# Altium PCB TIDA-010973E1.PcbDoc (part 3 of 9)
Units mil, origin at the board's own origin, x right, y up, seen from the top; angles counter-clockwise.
Board outline 5166 x 3669 mil, 8 copper layers (L01 - TOP, L02 - GND, L03 - SIG, L04 - GND, L05 - PWR, L06 - SIG, L07 - GND, L08 - BOTTOM), stack 61.7 mil thick; 677 components, 493 nets, 2522 pads, 1424 vias.
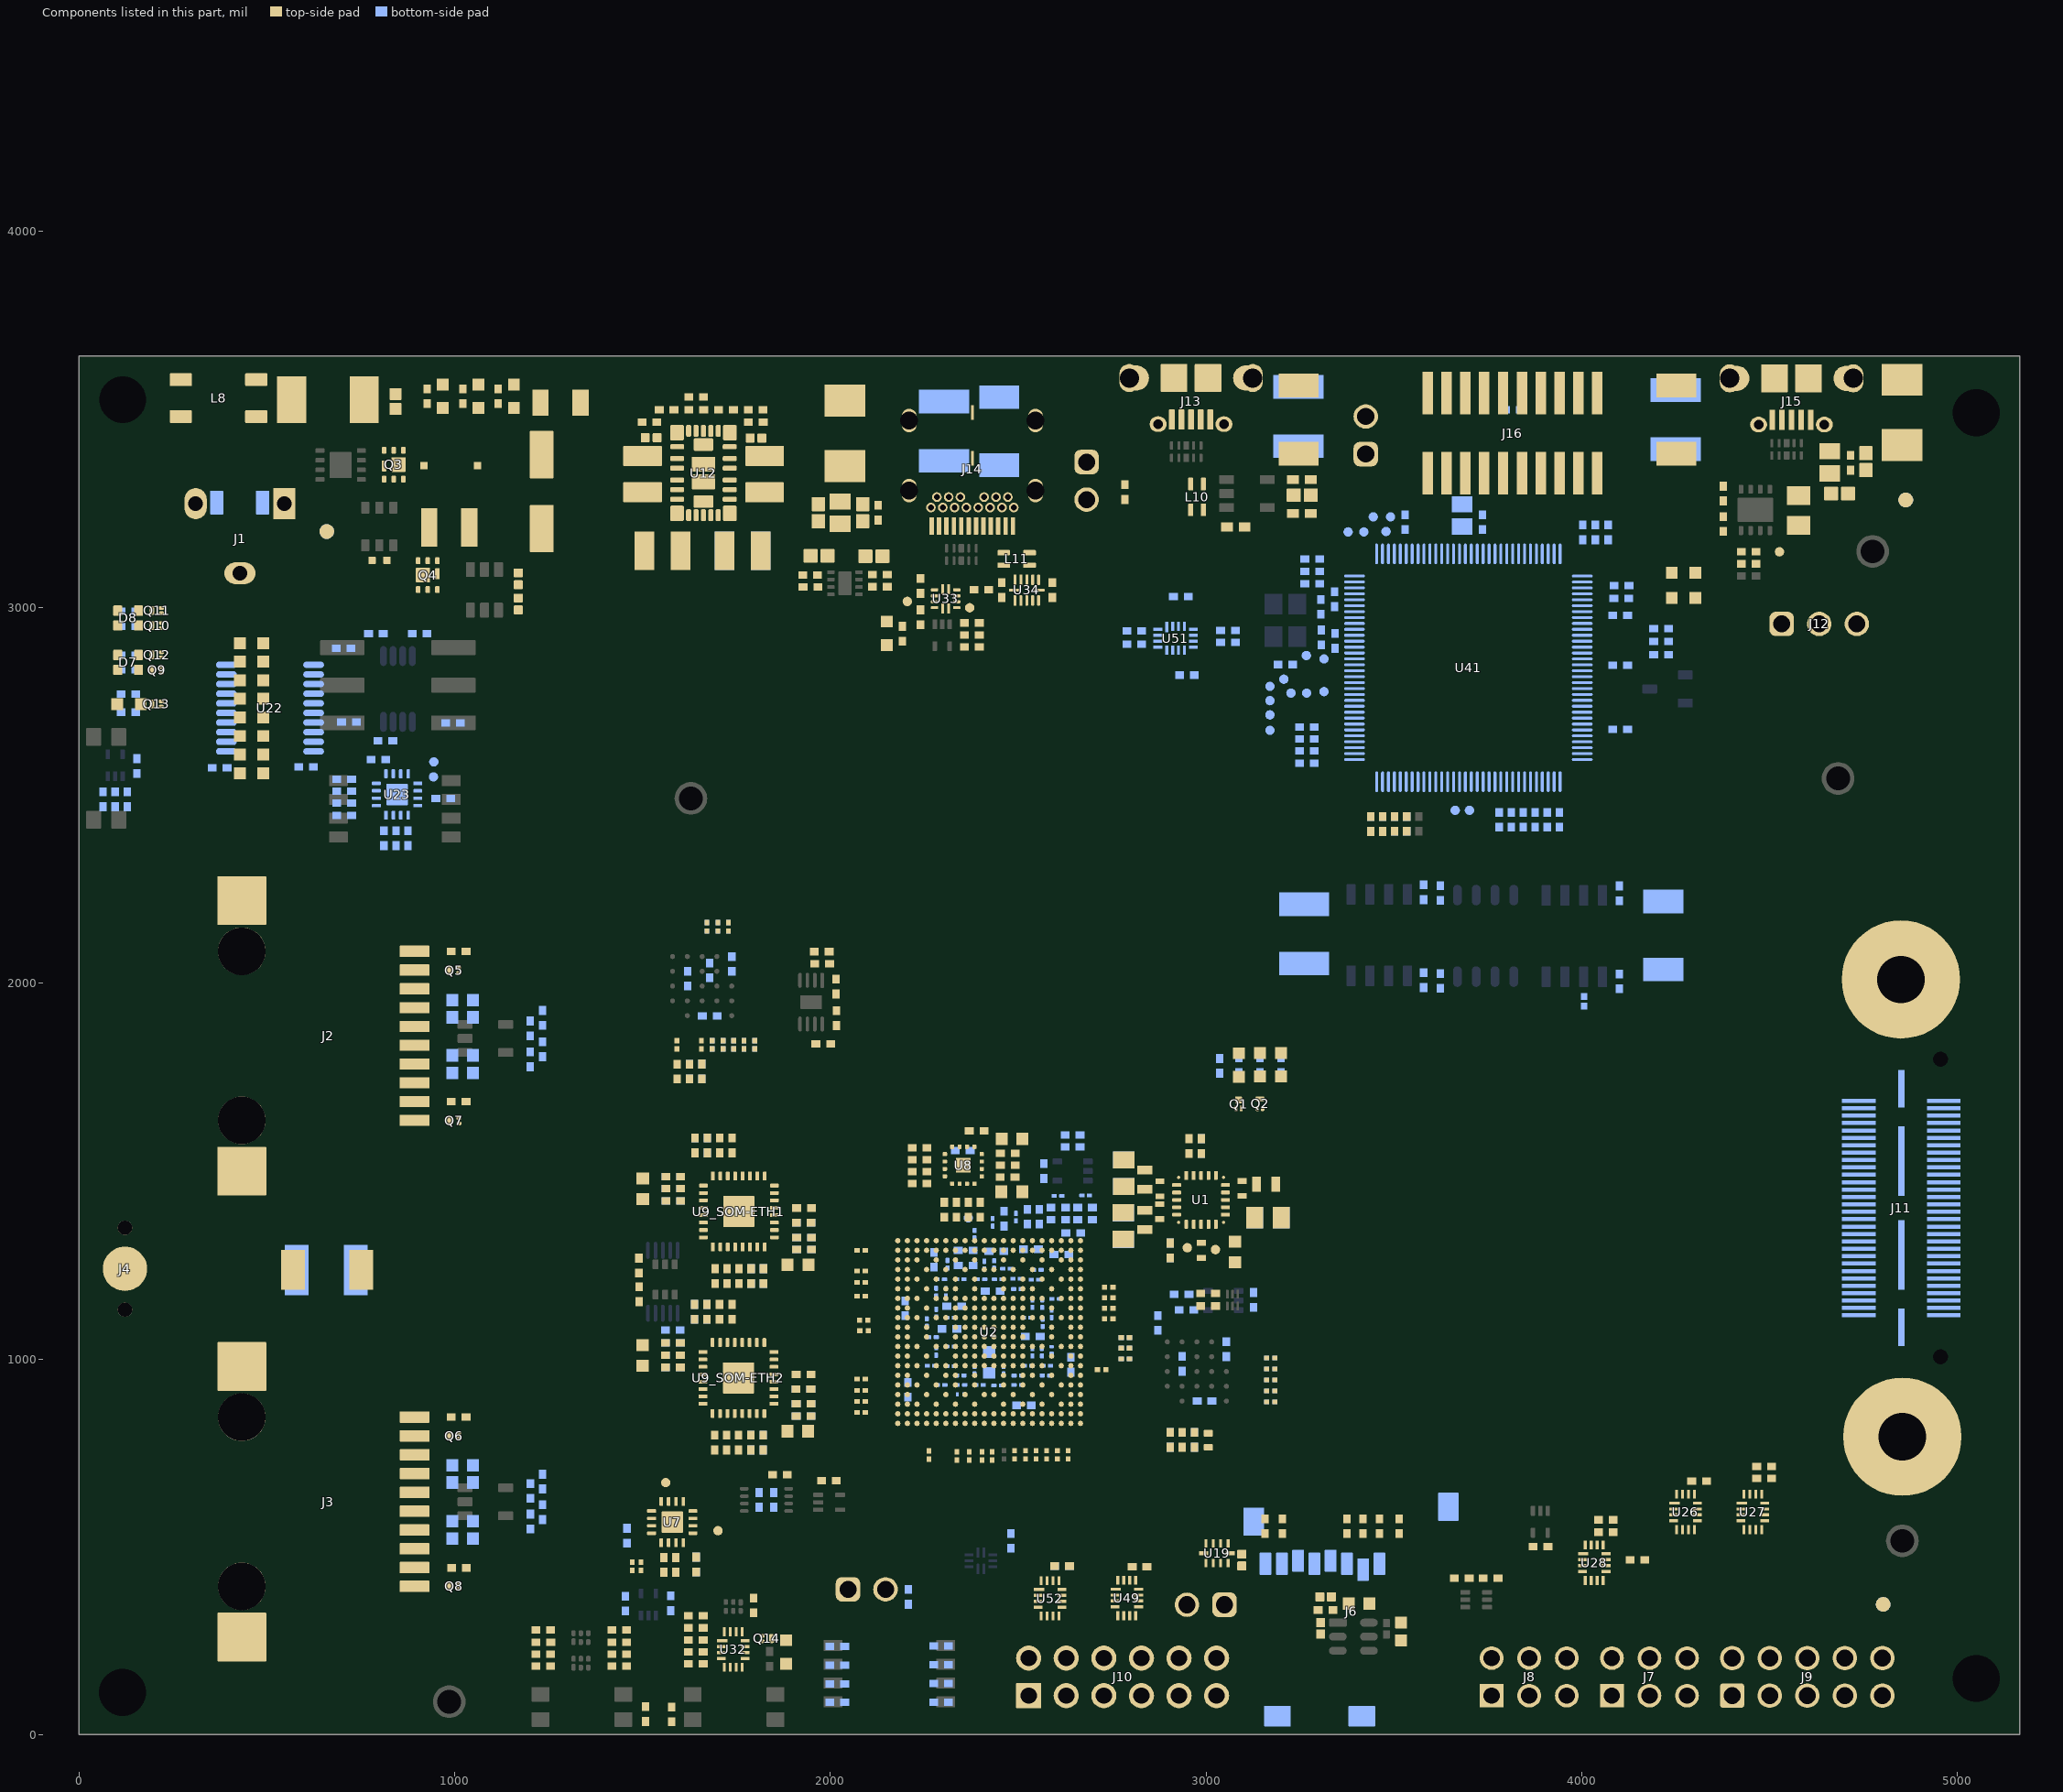
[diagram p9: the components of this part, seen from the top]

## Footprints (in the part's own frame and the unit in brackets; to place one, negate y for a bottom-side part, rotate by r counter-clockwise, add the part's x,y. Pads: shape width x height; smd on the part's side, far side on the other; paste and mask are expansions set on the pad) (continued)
PDT0128A [mm] "Thin QFP, 128-Leads, Body 14x14mm, Pitch 0.4mm"
  oval 1.4x0.2 smd: 1(-7.7,6.2) 2(-7.7,5.8) 3(-7.7,5.4) 4(-7.7,5) 5(-7.7,4.6) 6(-7.7,4.2) 7(-7.7,3.8) 8(-7.7,3.4) 9(-7.7,3) 10(-7.7,2.6) 11(-7.7,2.2) 12(-7.7,1.8) 13(-7.7,1.4) 14(-7.7,1) 15(-7.7,0.6) 16(-7.7,0.2) 17(-7.7,-0.2) 18(-7.7,-0.6) 19(-7.7,-1) 20(-7.7,-1.4) 21(-7.7,-1.8) 22(-7.7,-2.2) 23(-7.7,-2.6) 24(-7.7,-3) 25(-7.7,-3.4) 26(-7.7,-3.8) 27(-7.7,-4.2) 28(-7.7,-4.6) 29(-7.7,-5) 30(-7.7,-5.4) 31(-7.7,-5.8) 32(-7.7,-6.2) 65(7.7,-6.2) 66(7.7,-5.8) 67(7.7,-5.4) 68(7.7,-5) 69(7.7,-4.6) 70(7.7,-4.2) 71(7.7,-3.8) 72(7.7,-3.4) 73(7.7,-3) 74(7.7,-2.6) 75(7.7,-2.2) 76(7.7,-1.8) 77(7.7,-1.4) 78(7.7,-1) 79(7.7,-0.6) 80(7.7,-0.2) 81(7.7,0.2) 82(7.7,0.6) 83(7.7,1) 84(7.7,1.4) 85(7.7,1.8) 86(7.7,2.2) 87(7.7,2.6) 88(7.7,3) 89(7.7,3.4) 90(7.7,3.8) 91(7.7,4.2) 92(7.7,4.6) 93(7.7,5) 94(7.7,5.4) 95(7.7,5.8) 96(7.7,6.2)
  oval 0.2x1.4 smd: 33(-6.2,-7.7) 34(-5.8,-7.7) 35(-5.4,-7.7) 36(-5,-7.7) 37(-4.6,-7.7) 38(-4.2,-7.7) 39(-3.8,-7.7) 40(-3.4,-7.7) 41(-3,-7.7) 42(-2.6,-7.7) 43(-2.2,-7.7) 44(-1.8,-7.7) 45(-1.4,-7.7) 46(-1,-7.7) 47(-0.6,-7.7) 48(-0.2,-7.7) 49(0.2,-7.7) 50(0.6,-7.7) 51(1,-7.7) 52(1.4,-7.7) 53(1.8,-7.7) 54(2.2,-7.7) 55(2.6,-7.7) 56(3,-7.7) 57(3.4,-7.7) 58(3.8,-7.7) 59(4.2,-7.7) 60(4.6,-7.7) 61(5,-7.7) 62(5.4,-7.7) 63(5.8,-7.7) 64(6.2,-7.7) 97(6.2,7.7) 98(5.8,7.7) 99(5.4,7.7) 100(5,7.7) 101(4.6,7.7) 102(4.2,7.7) 103(3.8,7.7) 104(3.4,7.7) 105(3,7.7) 106(2.6,7.7) 107(2.2,7.7) 108(1.8,7.7) 109(1.4,7.7) 110(1,7.7) 111(0.6,7.7) 112(0.2,7.7) 113(-0.2,7.7) 114(-0.6,7.7) 115(-1,7.7) 116(-1.4,7.7) 117(-1.8,7.7) 118(-2.2,7.7) 119(-2.6,7.7) 120(-3,7.7) 121(-3.4,7.7) 122(-3.8,7.7) 123(-4.2,7.7) 124(-4.6,7.7) 125(-5,7.7) 126(-5.4,7.7) 127(-5.8,7.7) 128(-6.2,7.7)
  silkscreen extent -7.7,-6.3 6.3,6.99, body extent -8,-8 8,8, height 1.07
PW0020A_N [mm] "TSOP, 20-Leads, Body 6.5x4.4mm, Pitch 0.65mm, IPC Medium Density"
  oval 1.4x0.45 smd: 1(-2.95,2.925) 2(-2.95,2.275) 3(-2.95,1.625) 4(-2.95,0.975) 5(-2.95,0.325) 6(-2.95,-0.325) 7(-2.95,-0.975) 8(-2.95,-1.625) 9(-2.95,-2.275) 10(-2.95,-2.925) 11(2.95,-2.925) 12(2.95,-2.275) 13(2.95,-1.625) 14(2.95,-0.975) 15(2.95,-0.325) 16(2.95,0.325) 17(2.95,0.975) 18(2.95,1.625) 19(2.95,2.275) 20(2.95,2.925)
  Top Overlay keep-out lines w0.2: -1.85,-3.3 1.85,-3.3
  silkscreen extent -3.5,-3.3 1.85,3.4, body extent -3.21,-3.25 3.21,3.25, height 1
RDH0030A-MFG [mm]
  rrect22% 0.93x1.05 smd paste-1000 mask-1000: 1(-1.786,2.725) 8(-1.786,-2.725) 14(1.786,-2.725) 21(1.786,2.725)
  rrect57% 0.95x0.35 smd paste-1000 mask-1000: 2(-1.775,1.775) 3(-1.775,0.975) 4(-1.775,0.325) 5(-1.775,-0.475) 6(-1.775,-1.125) 7(-1.775,-1.775) 15(1.775,-1.775) 16(1.775,-1.125) 17(1.775,-0.475) 18(1.775,0.325) 19(1.775,0.975) 20(1.775,1.775)
  rrect57% 0.35x0.8 smd paste-1000 mask-1000: 9(-1,-2.85) 10(-0.5,-2.85) 11(0,-2.85) 12(0.5,-2.85) 13(1,-2.85) 22(1,2.85) 23(0.5,2.85) 24(0,2.85) 25(-0.5,2.85) 26(-1,2.85)
  rrect24% 1.35x0.84 smd paste-1000 mask-1000: 27(0,1.925) 30(0,-1.925)
  rrect12% 1.6x1 smd paste-1000 mask-1000: 28(0,0.6) 29(0,-0.6)
  L01 - TOP region: -0.85,-1.05 -0.85,1.05 -0.837,1.1 -0.8,1.137 -0.75,1.15 -0.75,1.15 0.75,1.15 0.8,1.137 0.837,1.1 0.85,1.05 0.85,1.05 0.85,-1.05 0.837,-1.1 0.8,-1.137 0.75,-1.15 0.75,-1.15 -0.75,-1.15 -0.8,-1.137 -0.837,-1.1 -0.85,-1.05
  silkscreen extent -2.95,-3.65 2.05,3.65, body extent -2.35,-3.35 2.35,3.35, height 0.25
RER0016A-MFG [mm] "Recommended Land Pattern"
  rrect36% 0.3x0.275 smd paste-1000 mask+0: 1(-1.25,0.75) 2(-1.25,0.25) 3(-1.25,-0.25) 4(-1.25,-0.75) 9(1.25,-0.75) 10(1.25,-0.25) 11(1.25,0.25) 12(1.25,0.75)
  rrect36% 0.275x0.3 smd paste-1000 mask+0: 5(-0.75,-1.25) 6(-0.25,-1.25) 7(0.25,-1.25) 8(0.75,-1.25) 13(0.75,1.25) 14(0.25,1.25) 15(-0.25,1.25) 16(-0.75,1.25)
  rrect10% 1x1 smd paste-1000 mask+0: 17(0,0)
  silkscreen extent -2.15,-1.55 1.55,1.55, body extent -1.5,-1.5 1.5,1.5, height 1.5
RGT0016A#1 [mm] "QFN, 16-Leads, Body 3x3mm, Pitch 0.5mm, Thermal Pad 1.45x1.45mm, TI Recommended"
  rrect42% 0.6x0.24 smd: 1(-1.4,0.75) 2(-1.4,0.25) 3(-1.4,-0.25) 4(-1.4,-0.75) 9(1.4,-0.75) 10(1.4,-0.25) 11(1.4,0.25) 12(1.4,0.75)
  rrect42% 0.24x0.6 smd: 5(-0.75,-1.4) 6(-0.25,-1.4) 7(0.25,-1.4) 8(0.75,-1.4) 13(0.75,1.4) 14(0.25,1.4) 15(-0.25,1.4) 16(-0.75,1.4)
  rrect7% 1.34x1.34 on Top Paste: 17(0,0)
  rrect7% 1.45x1.45 smd paste-0.725: 17(0,0)
  silkscreen extent -1.72,-1.73 1.72,1.73, body extent -1.5,-1.5 1.5,1.5, height 1
RGT0016A#2 [mm] "QFN, 16-Leads, Body 3x3mm, Pitch 0.5mm, Thermal Pad 1.45x1.45mm, TI Recommended"
  rrect42% 0.6x0.24 smd: 1(-1.4,0.75) 2(-1.4,0.25) 3(-1.4,-0.25) 4(-1.4,-0.75) 9(1.4,-0.75) 10(1.4,-0.25) 11(1.4,0.25) 12(1.4,0.75)
  rrect42% 0.24x0.6 smd: 5(-0.75,-1.4) 6(-0.25,-1.4) 7(0.25,-1.4) 8(0.75,-1.4) 13(0.75,1.4) 14(0.25,1.4) 15(-0.25,1.4) 16(-0.75,1.4)
  rrect7% 1.34x1.34 on Bottom Paste: 17(0,0)
  rrect7% 1.45x1.45 smd paste-0.725: 17(0,0)
  silkscreen extent -1.72,-1.73 1.72,1.73, body extent -1.5,-1.5 1.5,1.5, height 1
RHB0032M-MFG [mm] "Recommended Land Pattern"
  rrect40% 0.6x0.25 smd paste+0 mask+0: 1(-2.4,1.75) 2(-2.4,1.25) 3(-2.4,0.75) 4(-2.4,0.25) 5(-2.4,-0.25) 6(-2.4,-0.75) 7(-2.4,-1.25) 8(-2.4,-1.75) 17(2.4,-1.75) 18(2.4,-1.25) 19(2.4,-0.75) 20(2.4,-0.25) 21(2.4,0.25) 22(2.4,0.75) 23(2.4,1.25) 24(2.4,1.75)
  rrect40% 0.25x0.6 smd paste+0 mask+0: 9(-1.75,-2.4) 10(-1.25,-2.4) 11(-0.75,-2.4) 12(-0.25,-2.4) 13(0.25,-2.4) 14(0.75,-2.4) 15(1.25,-2.4) 16(1.75,-2.4) 25(1.75,2.4) 26(1.25,2.4) 27(0.75,2.4) 28(0.25,2.4) 29(-0.25,2.4) 30(-0.75,2.4) 31(-1.25,2.4) 32(-1.75,2.4)
  rrect5% 2.1x2.1 smd paste-1000 mask+0: 33(0,0)
  silkscreen extent -3.37,-2.55 2.55,2.55, body extent -2.8,-2.8 2.8,2.8, height 0.25
RSE0010A [mm] "QFN, 10-Leads, Body 1.5x2mm, Pitch 0.5mm, TI Recommended"
  rect 0.55x0.2 smd: 1(-0.675,0.75) 2(-0.675,0.25) 3(-0.675,-0.25) 4(-0.675,-0.75) 6(0.675,-0.75) 7(0.675,-0.25) 8(0.675,0.25) 9(0.675,0.75)
  rect 0.3x0.6 smd: 5(0,-0.9) 10(0,0.9)
  silkscreen extent -1.07,-1.17 0.77,1.18, body extent -0.77,-1.02 0.78,1.03, height 0.61
RSV0016A [mm] "QFN, 16-Leads, Body 1.8x2.6mm, Pitch 0.4mm, TI Recommended"
  rect 0.7x0.2 smd: 1(-0.75,0.6)
  rect 0.6x0.2 smd: 2(-0.8,0.2) 3(-0.8,-0.2) 4(-0.8,-0.6) 9(0.8,-0.6) 10(0.8,-0.2) 11(0.8,0.2) 12(0.8,0.6)
  rect 0.2x0.6 smd: 5(-0.6,-1.2) 6(-0.2,-1.2) 7(0.2,-1.2) 8(0.6,-1.2) 13(0.6,1.2) 14(0.2,1.2) 15(-0.2,1.2) 16(-0.6,1.2)
  silkscreen extent -1.08,-1.33 1.08,1.45, body extent -0.92,-1.32 0.92,1.33, height 0.56
RUT0012A [mm] "QFN, 12-Leads, Body 1.7x2mm, Pitch 0.4mm, TI Recommended"
  rrect50% 0.7x0.2 smd: 1(-0.7,0.8) 2(-0.7,0.4) 3(-0.7,0) 4(-0.7,-0.4) 5(-0.7,-0.8) 7(0.7,-0.8) 8(0.7,-0.4) 9(0.7,0) 10(0.7,0.4) 11(0.7,0.8)
  rrect50% 0.2x0.7 smd: 6(0,-0.85) 12(0,0.85)
  silkscreen extent -0.9,-1.2 0.9,1.2, body extent -0.85,-1 0.85,1, height 0.55
RWB0012A [mm] "QFN, 12-Leads, Body 1.6x1.6mm, Pitch 0.4mm"
  rrect57% 0.7x0.2 smd paste-0.1: 1(-0.65,0.2) 2(-0.65,-0.2) 7(0.65,-0.2) 8(0.65,0.2)
  rrect57% 0.2x0.5 smd: 3(-0.6,-0.75) 4(-0.2,-0.75) 5(0.2,-0.75) 6(0.6,-0.75) 9(0.6,0.75) 10(0.2,0.75) 11(-0.2,0.75) 12(-0.6,0.75)
  silkscreen extent -0.92,-0.91 0.92,0.91, body extent -0.8,-0.8 0.8,0.8, height 0.4
Samtec_FTR-110-51-x-D-06 [mm] "Header, 1.27mm, 10x2, SMT"
  rect 2.87x0.711 smd: 1(-2.705,5.715) 2(2.705,5.715) 3(-2.705,4.445) 4(2.705,4.445) 5(-2.705,3.175) 6(2.705,3.175) 7(-2.705,1.905) 8(2.705,1.905) 9(-2.705,0.635) 10(2.705,0.635) 11(-2.705,-0.635) 12(2.705,-0.635) 13(-2.705,-1.905) 14(2.705,-1.905) 15(-2.705,-3.175) 16(2.705,-3.175) 17(-2.705,-4.445) 18(2.705,-4.445) 19(-2.705,-5.715) 20(2.705,-5.715)
  silkscreen extent -2.49,-6.35 2.49,6.7, body extent -3.76,-6.35 3.76,6.35, height 8.64
Samtec_QSH-030-01-X-D-A [mm] "Receptacle, 0.5 mm, 30x2, TH"
  rect 2.27x0.279 smd: 1(-2.865,7.25) 2(2.865,7.25) 3(-2.865,6.75) 4(2.865,6.75) 5(-2.865,6.25) 6(2.865,6.25) 7(-2.865,5.75) 8(2.865,5.75) 9(-2.865,5.25) 10(2.865,5.25) 11(-2.865,4.75) 12(2.865,4.75) 13(-2.865,4.25) 14(2.865,4.25) 15(-2.865,3.75) 16(2.865,3.75) 17(-2.865,3.25) 18(2.865,3.25) 19(-2.865,2.75) 20(2.865,2.75) 21(-2.865,2.25) 22(2.865,2.25) 23(-2.865,1.75) 24(2.865,1.75) 25(-2.865,1.25) 26(2.865,1.25) 27(-2.865,0.75) 28(2.865,0.75) 29(-2.865,0.25) 30(2.865,0.25) 31(-2.865,-0.25) 32(2.865,-0.25) 33(-2.865,-0.75) 34(2.865,-0.75) 35(-2.865,-1.25) 36(2.865,-1.25) 37(-2.865,-1.75) 38(2.865,-1.75) 39(-2.865,-2.25) 40(2.865,-2.25) 41(-2.865,-2.75) 42(2.865,-2.75) 43(-2.865,-3.25) 44(2.865,-3.25) 45(-2.865,-3.75) 46(2.865,-3.75) 47(-2.865,-4.25) 48(2.865,-4.25) 49(-2.865,-4.75) 50(2.865,-4.75) 51(-2.865,-5.25) 52(2.865,-5.25) 53(-2.865,-5.75) 54(2.865,-5.75) 55(-2.865,-6.25) 56(2.865,-6.25) 57(-2.865,-6.75) 58(2.865,-6.75) 59(-2.865,-7.25) 60(2.865,-7.25)
  round 0 hole 1.02 unplated: MH1(2.67,10.065) MH2(2.67,-10.065)
  rect 0.43x2.54 smd: MP1(0,8.065) MP4(0,-8.065)
  rect 0.43x4.7 smd: MP2(0,3.175) MP3(0,-3.175)
  silkscreen extent -3.9,-10.66 3.62,10.66, body extent -3.75,-10.64 3.75,10.67, height 3.25
SloBlo452 [mm] "Littelfuse 452/4 Fuses, recommended land pattern"
  rect 1.96x3.15 smd: 1(-2.455,0) 2(2.455,0)
  silkscreen extent -3.75,-1.88 3.75,1.9, body extent -3.05,-1.35 3.05,1.34, height 2.69
SMB-Bi [mil] "Molded Diode, 2-Leads, Body 5.4x3.6mm, IPC Medium Density, based on OnSemi component dimensions"
  rect 85x107.99 smd: 1(-87.01,0) 2(87.01,0)
  silkscreen extent -125,-79 125,79, body extent -104,-73 104,73, height 89
TI_Stacked_Overlay_Small [mil]
  silkscreen extent -418,-98 418,98
TP_25MIL-SMT [mil]
  round 25 smd mask-2.5: 1(0,0)
VAF0024A-MFG [mm]
  round 0.207 smd paste+0 mask+0: 1(-1.519,1.519) 7(-1.519,-1.519) 13(1.519,-1.519) 19(1.519,1.519)
  rrect40% 0.6x0.25 smd paste+0 mask+0: 2(-1.65,1) 3(-1.65,0.5) 4(-1.65,0) 5(-1.65,-0.5) 6(-1.65,-1) 14(1.65,-1) 15(1.65,-0.5) 16(1.65,0) 17(1.65,0.5) 18(1.65,1)
  rrect40% 0.25x0.6 smd paste+0 mask+0: 8(-1,-1.65) 9(-0.5,-1.65) 11(0.5,-1.65) 12(1,-1.65) 20(1,1.65) 21(0.5,1.65) 23(-0.5,1.65) 24(-1,1.65)
  rrect40% 0.25x0.6 smd paste+0 mask-1000: 10(0,-1.65) 22(0,1.65)
  L01 - TOP region: -0.5,0.286 -0.493,0.311 -0.475,0.33 -0.45,0.336 -0.45,0.336 -0.1,0.336 -0.1,1.357 -0.118,1.375 -0.125,1.4 -0.125,1.4 -0.125,1.9 -0.118,1.925 -0.1,1.943 -0.075,1.95 -0.075,1.95 0.075,1.95 0.1,1.943 0.118,1.925 0.125,1.9 0.125,1.9 0.125,1.4 0.118,1.375 0.1,1.357 0.1,1.357 0.1,0.336 0.45,0.336 0.475,0.33 0.493,0.311 0.5,0.287 0.5,0.286 0.5,-0.286 0.493,-0.311 0.475,-0.33 0.45,-0.336 0.45,-0.336 0.1,-0.336 0.1,-1.357 0.118,-1.375 0.125,-1.4 0.125,-1.4 0.125,-1.9 0.118,-1.925 0.1,-1.943 0.075,-1.95 0.075,-1.95 -0.075,-1.95 -0.1,-1.943 -0.118,-1.925 -0.125,-1.9 -0.125,-1.9 -0.125,-1.4 -0.118,-1.375 -0.1,-1.357 -0.1,-1.357 -0.1,-0.336 -0.45,-0.336 -0.475,-0.33 -0.493,-0.311 -0.5,-0.287 -0.5,-0.286
  L01 - TOP region: -1.9,1.375 -1.919,1.379 -1.935,1.39 -1.946,1.406 -1.95,1.425 -1.95,1.425 -1.95,1.55 -1.943,1.575 -1.925,1.593 -1.9,1.6 -1.9,1.6 -1.6,1.6 -1.6,1.9 -1.593,1.925 -1.575,1.943 -1.55,1.95 -1.55,1.95 -1.425,1.95 -1.406,1.946 -1.39,1.935 -1.379,1.919 -1.375,1.9 -1.375,1.9 -1.375,1.425 -1.379,1.406 -1.39,1.39 -1.406,1.379 -1.425,1.375 -1.425,1.375
  L01 - TOP region: -1.9,-1.375 -1.919,-1.379 -1.935,-1.39 -1.946,-1.406 -1.95,-1.425 -1.95,-1.425 -1.95,-1.55 -1.946,-1.569 -1.935,-1.585 -1.919,-1.596 -1.9,-1.6 -1.9,-1.6 -1.6,-1.6 -1.6,-1.9 -1.596,-1.919 -1.585,-1.935 -1.569,-1.946 -1.55,-1.95 -1.55,-1.95 -1.425,-1.95 -1.4,-1.943 -1.382,-1.925 -1.375,-1.9 -1.375,-1.9 -1.375,-1.425 -1.379,-1.406 -1.39,-1.39 -1.406,-1.379 -1.425,-1.375 -1.425,-1.375
  L01 - TOP region: 1.9,-1.375 1.919,-1.379 1.935,-1.39 1.946,-1.406 1.95,-1.425 1.95,-1.425 1.95,-1.55 1.946,-1.569 1.935,-1.585 1.919,-1.596 1.9,-1.6 1.9,-1.6 1.6,-1.6 1.6,-1.9 1.596,-1.919 1.585,-1.935 1.569,-1.946 1.55,-1.95 1.55,-1.95 1.425,-1.95 1.4,-1.943 1.382,-1.925 1.375,-1.9 1.375,-1.9 1.375,-1.425 1.379,-1.406 1.39,-1.39 1.406,-1.379 1.425,-1.375 1.425,-1.375
  L01 - TOP region: 1.9,1.375 1.919,1.379 1.935,1.39 1.946,1.406 1.95,1.425 1.95,1.425 1.95,1.55 1.946,1.569 1.935,1.585 1.919,1.596 1.9,1.6 1.9,1.6 1.6,1.6 1.6,1.9 1.596,1.919 1.585,1.935 1.569,1.946 1.55,1.95 1.55,1.95 1.425,1.95 1.4,1.943 1.382,1.925 1.375,1.9 1.375,1.9 1.375,1.425 1.379,1.406 1.39,1.39 1.406,1.379 1.425,1.375 1.425,1.375
  silkscreen extent -2.62,-2.15 2.15,2.15, body extent -2.05,-2.05 2.05,2.05, height 0.25
WE-PMCI_0603LP [mm] "SMD, 2-Leads, Body 1.6x0.8mm"
  rect 0.6x1 smd: 1(-0.65,0) 2(0.65,0)
  silkscreen extent -0.05,-0.5 0.05,0.5, body extent -0.8,-0.4 0.8,0.4, height 0.8
WE-TPC-S [mm] "Wurth Elektronik recommended land pattern"
  rect 0.5x0.5 smd: 1(-1.8,0) 2(1.8,0)
  L01 - TOP region: -0.55,1.185 -0.658,1.14 -0.931,0.931 -1.14,0.658 -1.271,0.341 -1.316,0 -1.271,-0.341 -1.14,-0.658 -0.931,-0.931 -0.658,-1.14 -0.55,-1.185 -0.55,-2.15 -2.15,-2.15 -2.15,2.15 -0.55,2.15
  L01 - TOP region: 2.15,-2.15 0.55,-2.15 0.55,-1.185 0.658,-1.14 0.931,-0.931 1.14,-0.658 1.271,-0.341 1.316,0 1.271,0.341 1.14,0.658 0.931,0.931 0.658,1.14 0.55,1.185 0.55,2.15 2.15,2.15
  silkscreen extent -2.35,-2.35 2.35,2.35, body extent -2.05,-2.05 2.05,2.05, height 1.8
WEEE_Minimum [mil] "WEEElie bin"
  silkscreen extent -95,-172 99,104
WL-SMCW_GREEN [mm] "WURTH"
  rect 0.8x0.8 smd: 1(-0.8,0) 2(0.8,0)
  silkscreen extent -1.9,-0.8 1.2,0.8, body extent -0.85,-0.45 0.85,0.45, height 0.8
WL-SMCW_RED [mm] "WURTH"
  rect 0.8x0.8 smd: 1(-0.8,0) 2(0.8,0)
  silkscreen extent -1.9,-0.8 1.2,0.8, body extent -0.85,-0.45 0.85,0.45, height 0.8
Wurth_60900213421 [mil] "Shunt, 2.54mm, Black"
  round 1 on Mech3: 0(0,0)
  body extent -98,-48 98,48, height 338
WURTH_61300211121 [mm] "Header, 2.54mm, 2x1, TH"
  rrect50% 1.65x1.65 hole 1.15: 1(-1.27,0)
  round 1.65 hole 1.15: 2(1.27,0)
  body extent -2.54,-1.27 2.54,1.27, height 8.54
WURTH_61300311121 [mm] "Header, 2.54mm, 3x1, TH"
  rrect50% 1.65x1.65 hole 1.15: 1(-2.54,0)
  round 1.65 hole 1.15: 2(0,0) 3(2.54,0)
  body extent -3.81,-1.27 3.81,1.27, height 8.54
Wurth_61300621121 [mm] "Header, 2.54mm, 3x2, TH"
  rect 1.6x1.6 hole 1.1: 1(-1.27,2.54)
  round 1.6 hole 1.1: 2(1.27,2.54) 3(-1.27,0) 4(1.27,0) 5(-1.27,-2.54) 6(1.27,-2.54)
  silkscreen extent -2.8,-3.82 2.54,3.8, body extent -2.54,-3.82 2.54,3.8, height 7.27
WURTH_61301021121 [mm] "Header, 2.54mm, 5x2, TH"
  rrect25% 1.65x1.65 hole 1.15: 1(-5.08,-1.27)
  round 1.65 hole 1.15: 2(-5.08,1.27) 3(-2.54,-1.27) 4(-2.54,1.27) 5(0,-1.27) 6(0,1.27) 7(2.54,-1.27) 8(2.54,1.27) 9(5.08,-1.27) 10(5.08,1.27)
  silkscreen extent -6.35,-2.9 6.35,2.54, body extent -6.35,-2.54 6.35,2.54, height 8.54
YJC0003A [mm] "TI"
  rrect50% 0.25x0.2 on Top Paste: 0(-0.325,-0.2) 0(-0.325,0.2)
  rrect80% 0.35x0.25 smd paste-0.13 mask-0.05: 1(-0.325,0.175) 2(-0.325,-0.175)
  rrect57% 0.35x0.6 smd paste-0.05 mask-0.05: 3(0.325,0)
  body extent -0.5,-0.3 0.5,0.3, height 0.35
ZFG0304A-MFG [mm] "Recommended Land Pattern"
  round 0.35 smd paste+0 mask-1000: A1(-6.175,6.175) A2(-5.525,6.175) A3(-4.875,6.175) A4(-4.225,6.175) A5(-3.575,6.175) A6(-2.925,6.175) A7(-2.275,6.175) A8(-1.625,6.175) A9(-0.975,6.175) A10(-0.325,6.175) A11(0.325,6.175) A12(0.975,6.175) A13(1.625,6.175) A14(2.275,6.175) A15(2.925,6.175) A16(3.575,6.175) A17(4.225,6.175) A18(4.875,6.175) A19(5.525,6.175) A20(6.175,6.175) B1(-6.175,5.525) B2(-5.525,5.525) B3(-4.875,5.525) B4(-4.225,5.525) B5(-3.575,5.525) B6(-2.925,5.525) B7(-2.275,5.525) B8(-1.625,5.525) B9(-0.975,5.525) B10(-0.325,5.525) B11(0.325,5.525) B12(0.975,5.525) B13(1.625,5.525) B14(2.275,5.525) B15(2.925,5.525) B16(3.575,5.525) B17(4.225,5.525) B18(4.875,5.525) B19(5.525,5.525) B20(6.175,5.525) C1(-6.175,4.875) C2(-5.525,4.875) C3(-4.875,4.875) C5(-3.575,4.875) C7(-2.275,4.875) C9(-0.975,4.875) C12(0.975,4.875) C14(2.275,4.875) C16(3.575,4.875) C18(4.875,4.875) C19(5.525,4.875) C20(6.175,4.875) D1(-6.175,4.225) D2(-5.525,4.225) D4(-4.225,4.225) D6(-2.925,4.225) D8(-1.625,4.225) D10(-0.325,4.225) D11(0.325,4.225) D13(1.625,4.225) D15(2.925,4.225) D17(4.225,4.225) D19(5.525,4.225) D20(6.175,4.225) E1(-6.175,3.575) E2(-5.525,3.575) E3(-4.875,3.575) E5(-3.575,3.575) E7(-2.275,3.575) E9(-0.975,3.575) E12(0.975,3.575) E14(2.275,3.575) E16(3.575,3.575) E18(4.875,3.575) E19(5.525,3.575) E20(6.175,3.575) F1(-6.175,2.925) F2(-5.525,2.925) F4(-4.225,2.925) F6(-2.925,2.925) F7(-2.275,2.925) F9(-0.975,2.925) F12(0.975,2.925) F14(2.275,2.925) F15(2.925,2.925) F17(4.225,2.925) F19(5.525,2.925) F20(6.175,2.925) G1(-6.175,2.275) G2(-5.525,2.275) G3(-4.875,2.275) G5(-3.575,2.275) G6(-2.925,2.275) G7(-2.275,2.275) G8(-1.625,2.275) G9(-0.975,2.275) G10(-0.325,2.275) G11(0.325,2.275) G12(0.975,2.275) G13(1.625,2.275) G14(2.275,2.275) G15(2.925,2.275) G16(3.575,2.275) G18(4.875,2.275) G19(5.525,2.275) G20(6.175,2.275) H1(-6.175,1.625) H2(-5.525,1.625) H4(-4.225,1.625) H7(-2.275,1.625) H8(-1.625,1.625) H9(-0.975,1.625) H10(-0.325,1.625) H11(0.325,1.625) H12(0.975,1.625) H13(1.625,1.625) H14(2.275,1.625) H17(4.225,1.625) H19(5.525,1.625) H20(6.175,1.625) J1(-6.175,0.975) J2(-5.525,0.975) J3(-4.875,0.975) J5(-3.575,0.975) J6(-2.925,0.975) J7(-2.275,0.975) J8(-1.625,0.975) J9(-0.975,0.975) J10(-0.325,0.975) J11(0.325,0.975) J12(0.975,0.975) J13(1.625,0.975) J14(2.275,0.975) J15(2.925,0.975) J16(3.575,0.975) J18(4.875,0.975) J19(5.525,0.975) J20(6.175,0.975) K1(-6.175,0.325) K2(-5.525,0.325) K4(-4.225,0.325) K7(-2.275,0.325) K8(-1.625,0.325) K9(-0.975,0.325) K10(-0.325,0.325) K11(0.325,0.325) K12(0.975,0.325) K13(1.625,0.325) K14(2.275,0.325) K17(4.225,0.325) K19(5.525,0.325) K20(6.175,0.325) L1(-6.175,-0.325) L2(-5.525,-0.325) L4(-4.225,-0.325) L7(-2.275,-0.325) L8(-1.625,-0.325) L9(-0.975,-0.325) L10(-0.325,-0.325) L11(0.325,-0.325) L12(0.975,-0.325) L13(1.625,-0.325) L14(2.275,-0.325) L17(4.225,-0.325) L19(5.525,-0.325) L20(6.175,-0.325) M1(-6.175,-0.975) M2(-5.525,-0.975) M3(-4.875,-0.975) M5(-3.575,-0.975) M6(-2.925,-0.975) M7(-2.275,-0.975) M8(-1.625,-0.975) M9(-0.975,-0.975) M10(-0.325,-0.975) M11(0.325,-0.975) M12(0.975,-0.975) M13(1.625,-0.975) M14(2.275,-0.975) M15(2.925,-0.975) M16(3.575,-0.975) M18(4.875,-0.975) M19(5.525,-0.975) M20(6.175,-0.975) N1(-6.175,-1.625) N2(-5.525,-1.625) N4(-4.225,-1.625) N7(-2.275,-1.625) N8(-1.625,-1.625) N9(-0.975,-1.625) N10(-0.325,-1.625) N11(0.325,-1.625) N12(0.975,-1.625) N13(1.625,-1.625) N14(2.275,-1.625) N17(4.225,-1.625) N19(5.525,-1.625) N20(6.175,-1.625) P1(-6.175,-2.275) P2(-5.525,-2.275) P3(-4.875,-2.275) P5(-3.575,-2.275) P6(-2.925,-2.275) P7(-2.275,-2.275) P8(-1.625,-2.275) P9(-0.975,-2.275) P10(-0.325,-2.275) P11(0.325,-2.275) P12(0.975,-2.275) P13(1.625,-2.275) P14(2.275,-2.275) P15(2.925,-2.275) P16(3.575,-2.275) P18(4.875,-2.275) P19(5.525,-2.275) P20(6.175,-2.275) R1(-6.175,-2.925) R2(-5.525,-2.925) R4(-4.225,-2.925) R6(-2.925,-2.925) R7(-2.275,-2.925) R9(-0.975,-2.925) R12(0.975,-2.925) R14(2.275,-2.925) R15(2.925,-2.925) R17(4.225,-2.925) R19(5.525,-2.925) R20(6.175,-2.925) T1(-6.175,-3.575) T2(-5.525,-3.575) T3(-4.875,-3.575) T5(-3.575,-3.575) T7(-2.275,-3.575) T9(-0.975,-3.575) T12(0.975,-3.575) T14(2.275,-3.575) T16(3.575,-3.575) T18(4.875,-3.575) T19(5.525,-3.575) T20(6.175,-3.575) U1(-6.175,-4.225) U2(-5.525,-4.225) U4(-4.225,-4.225) U6(-2.925,-4.225) U8(-1.625,-4.225) U10(-0.325,-4.225) U11(0.325,-4.225) U13(1.625,-4.225) U15(2.925,-4.225) U17(4.225,-4.225) U19(5.525,-4.225) U20(6.175,-4.225) V1(-6.175,-4.875) V2(-5.525,-4.875) V3(-4.875,-4.875) V5(-3.575,-4.875) V7(-2.275,-4.875) V9(-0.975,-4.875) V12(0.975,-4.875) V14(2.275,-4.875) V16(3.575,-4.875) V18(4.875,-4.875) V19(5.525,-4.875) V20(6.175,-4.875) W1(-6.175,-5.525) W2(-5.525,-5.525) W3(-4.875,-5.525) W4(-4.225,-5.525) W5(-3.575,-5.525) W6(-2.925,-5.525) W7(-2.275,-5.525) W8(-1.625,-5.525) W9(-0.975,-5.525) W10(-0.325,-5.525) W11(0.325,-5.525) W12(0.975,-5.525) W13(1.625,-5.525) W14(2.275,-5.525) W15(2.925,-5.525) W16(3.575,-5.525) W17(4.225,-5.525) W18(4.875,-5.525) W19(5.525,-5.525) W20(6.175,-5.525) Y1(-6.175,-6.175) Y2(-5.525,-6.175) Y3(-4.875,-6.175) Y4(-4.225,-6.175) Y5(-3.575,-6.175) Y6(-2.925,-6.175) Y7(-2.275,-6.175) Y8(-1.625,-6.175) Y9(-0.975,-6.175) Y10(-0.325,-6.175) Y11(0.325,-6.175) Y12(0.975,-6.175) Y13(1.625,-6.175) Y14(2.275,-6.175) Y15(2.925,-6.175) Y16(3.575,-6.175) Y17(4.225,-6.175) Y18(4.875,-6.175) Y19(5.525,-6.175) Y20(6.175,-6.175)
  silkscreen extent -7.38,-6.78 6.78,6.77, body extent -6.63,-6.63 6.63,6.63, height 1.3

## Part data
C1 C2 C3 C4 C5 C6 C7 C8 C9 C10 C11 C12 C13 C17 C18 C19 C27 C28 C29 C30 C31 C32 C33 C34 C40 C41 C42 C45 C48 C52 C53 C54 C55 C59 C60 C190 C198 C199 C200 C201 C202 C203 C204 C205 C209 C210 C213 C215 C217: library part CMP-0049180-1, "0.1 µF ±10% 25V Ceramic Capacitor X5R 0201 (0603 Metric)", Digikey Part Number=732-885012104005CT-ND, Manufacturer="Wurth Electronics", Mouser Part Number=710-885012104005, Operating Temperature Range="-55°C to +85°C", TempCo=15%, Temperature Characteristic=X5R, Tolerance_%=10%, ValueDisplayed=100nF
C14 C15 C16 C35 C36 C37 C38 C39 C49 C50 C51 C56 C57 C58 C212 C214 C216: library part CMP-0006265-2, "CAP, CERM, 3.3 uF, 10 V, +/- 10%, X5R, 0402", Cap_Case=0402, Manufacturer=TDK, Supplier Part Number 1=445-13819-1-ND, TempCo=X5R, Tolerance_%=10%, Value1="0.004157 ohm", Value2=10V, ValueDisplayed=3.3uF
C20 C21 C26 C43 C188 C189: library part CMP-0078153-1, "CAP, CERM, 22 µF, 10 V,+/- 20%, X5R, 0805", Cap_Case=0805, Manufacturer="Wurth Elektronik", Supplier Part Number 1=732-7621-1-ND, TempCo=X5R, Tolerance_%=20%, Value2=10V, ValueDisplayed=22µF
C22 C23 C24 C25: library part CMP-0006268-2, "CAP, CERM, 4.7 uF, 10 V, +/- 10%, X5R, 0402", Cap_Case=0402_065, Manufacturer=TDK, Supplier Part Number 1=445-13820-1-ND, TempCo=X5R, Tolerance_%=10%, Value1="0.003417 ohm", Value2=10V, ValueDisplayed=4.7uF
C44: library part CMP-0006825-5, "CAP, CERM, 2.2 uF, 16 V, +/- 20%, X5R, 0603", Cap_Case=0603, Manufacturer="Wurth Elektronik", Supplier Part Number 1=732-7915-1-ND, TempCo=X5R, Tolerance_%=20%, Value1=Unknown, Value2=16V, ValueDisplayed=2.2uF
C46: library part CMP-0088282-2, "4.7µF ±10% 50V Ceramic Capacitor X7R 1206 (3216 Metric)", Manufacturer="Wurth Electronics", TempCo=15%, Tolerance_%=10%, ValueDisplayed=4.7uF
C61 C62 C111 C112 C113 C115 C116 C120 C121 C122 C123 C124 C172 C173 C174 C175 C176 C177 C178 C179 C192 C207 C208: library part CMP-0006221-2, "CAP, CERM, 0.1 uF, 10 V, +/- 20%, X5R, 0402", Cap_Case=0402, Manufacturer="Wurth Elektronik", Supplier Part Number 1=732-7487-1-ND, TempCo=X5R, Tolerance_%=20%, Value1=Unknown, Value2=10V, ValueDisplayed=0.1uF
C63 C64 C65 C66 C67 C68 C70_SOM-ETH1 C70_SOM-ETH2 C74_SOM-ETH1 C74_SOM-ETH2 C82 C83 C84 C86 C117 C118 C119 C139 C145 C146 C147 C148 C149 C150 C152 C154 C155 C162 C164 C167 C168 C171 C183 C184 C185 C186 C196 C197 C211 C218 C219: library part CMP-0006228-2, "CAP, CERM, 0.1 uF, 16 V, +/- 10%, X7R, 0402", Cap_Case=0402, Manufacturer="Wurth Elektronik", Supplier Part Number 1=732-7532-1-ND, TempCo=X7R, Tolerance_%=10%, Value1=Unknown, Value2=16V, ValueDisplayed=0.1uF
C69_SOM-ETH1 C69_SOM-ETH2 C73_SOM-ETH1 C73_SOM-ETH2: library part CMP-0006227-2, "CAP, CERM, 0.01 uF, 16 V, +/- 10%, X7R, 0402", Cap_Case=0402, Manufacturer="Wurth Elektronik", Supplier Part Number 1=710-885012205031, TempCo=X7R, Tolerance_%=10%, Value1=Unknown, Value2=16V, ValueDisplayed=0.01uF
C71_SOM-ETH1 C71_SOM-ETH2 C75_SOM-ETH1 C75_SOM-ETH2 C153 C163 C170 C191_SOM-ETH1 C191_SOM-ETH2: library part CMP-0064924-2, "CAP, CERM, 1 uF, 10 V,+/- 20%, X5R, 0402", Cap_Case=0402, Manufacturer="Wurth Elektronik", Supplier Part Number 1=732-7489-1-ND, TempCo=X5R, Tolerance_%=20%, Value1=Unknown, Value2=10V, ValueDisplayed=1uF
C72_SOM-ETH1 C72_SOM-ETH2 C76_SOM-ETH1 C76_SOM-ETH2: library part CMP-0006564-3, "CAP, CERM, 10 uF, 10 V, +/- 20%, X5R, 0402", Cap_Case=0402, Manufacturer=MuRata, TempCo=X5R, Tolerance_%=20%, Value1=Unknown, Value2=10V, ValueDisplayed=10uF
C77_SOM-ETH1 C77_SOM-ETH2 C78_SOM-ETH1 C78_SOM-ETH2 C79_SOM-ETH1 C79_SOM-ETH2 C80_SOM-ETH1 C80_SOM-ETH2: library part CMP-0006472-2, "CAP, CERM, 4.7 pF, 50 V, +/- 5%, C0G/NP0, 0402", Cap_Case=0402, Manufacturer=MuRata, Supplier Part Number 1=81-GRM1555C1H4R7CA1D, TempCo=C0G/NP0, Tolerance_%=5%, Value1=Unknown, Value2=50V, ValueDisplayed=4.7pF
C81_SOM-ETH1 C81_SOM-ETH2: library part CMP-0006224-2, "CAP, CERM, 2200 pF, 10 V, +/- 10%, X7R, 0402", Cap_Case=0402, Manufacturer="Wurth Elektronik", Supplier Part Number 1=732-7503-1-ND, TempCo=X7R, Tolerance_%=10%, Value1=Unknown, Value2=10V, ValueDisplayed=2200pF
C85 C180 C182: library part CMP-0120207-1, "10 µF ±20% 10V Ceramic Capacitor X5R 0402 (1005 Metric)", Manufacturer=Murata, Operating Temperature Range="-55°C to +85°C", TempCo=15%, Temperature Characteristic=X5R, Tolerance_%=20%, ValueDisplayed=10uF
C87: library part CMP-0006347-2, "CAP, CERM, 1 uF, 16 V, +/- 10%, X5R, 0402", Cap_Case=0402, Manufacturer="Taiyo Yuden", Supplier Part Number 1=587-3709-2-ND, TempCo=X5R, Tolerance_%=10%, Value1=Unknown, Value2=16V, ValueDisplayed=1uF
C88 C89 C90: library part CMP-0096740-1, "22 µF ±10% 25V Ceramic Capacitor X7R 1210 (3225 Metric)", Manufacturer=Wurth, Operating Temperature Range="-55°C to +125°C", TempCo=15%, Temperature Characteristic=X7R, Tolerance_%=10%, ValueDisplayed=22uF
C91: library part CMP-0076702-1, "CAP, AL, 47 µF, 35 V, +/- 20%, 0.26 ohm, AEC-Q200 Grade 2, SMD", Cap_Case=6.3x5.8mm, Manufacturer=Panasonic, Supplier Part Number 1=PCE4552CT-ND, Tolerance_%=20%, Value1="0.26 ohm", Value2=35V, ValueDisplayed=47µF
C92 C93 C97 C98 C100 C101 C193: library part CMP-0096737-1, "100 nF ±10% 50V Ceramic Capacitor X7R 0402 (1005 Metric)", Manufacturer=Wurth, Operating Temperature Range="-55°C to +125°C", TempCo=15%, Temperature Characteristic=X7R, Tolerance_%=10%, ValueDisplayed=100nF
C94 C95: library part CMP-0096739-1, "4.7 µF ±10% 50V Ceramic Capacitor X7R 1210 (3225 Metric)", Digikey Part Number=732-7386-1-ND, Manufacturer=Wurth, Mouser Part Number=710-885012209048, Operating Temperature Range="-55°C to +125°C", TempCo=15%, Temperature Characteristic=X7R, Tolerance_%=10%, ValueDisplayed=4.7uF
C96: library part CMP-0009226-3, "CAP, CERM, 10 uF, 50 V, +/- 10%, X7R, 1210", Cap_Case=1210, Manufacturer=MuRata, Supplier Part Number 1=490-6544-1-ND, TempCo=X7R, Tolerance_%=10%, Value1=Unknown, Value2=50V, ValueDisplayed=10uF
C99: library part CMP-0064912-2, "CAP, CERM, 22 pF, 10 V,+/- 5%, C0G/NP0, 0402", Cap_Case=0402, Manufacturer="Wurth Elektronik", Supplier Part Number 1=732-7427-1-ND, TempCo=C0G/NP0, Tolerance_%=5%, Value1=Unknown, Value2=10V, ValueDisplayed=22pF
C102 C103 C106 C107: library part CMP-0006831-4, "CAP, CERM, 1 uF, 16 V, +/- 10%, X7R, 0603", Cap_Case=0603, Manufacturer="Wurth Elektronik", Supplier Part Number 1=710-885012206052, TempCo=X7R, Tolerance_%=10%, Value1=Unknown, Value2=16V, ValueDisplayed=1uF
C104 C105 C108 C109: library part CMP-0006829-4, "CAP, CERM, 0.1 uF, 16 V, +/- 10%, X7R, 0603", Cap_Case=0603, Manufacturer="Wurth Elektronik", Supplier Part Number 1=710-885012206046, TempCo=X7R, Tolerance_%=10%, Value1=Unknown, Value2=16V, ValueDisplayed=0.1uF
C110 C129 C138 C141 C151: library part CMP-0009293-2, "CAP, CERM, 1000 pF, 2000 V, +/- 10%, X7R, 1812", Cap_Case=1812, Manufacturer=AVX, Supplier Part Number 1=581-1812GC102KA11A, TempCo=X7R, Tolerance_%=10%, Value1=Unknown, Value2=2000V, ValueDisplayed=1000pF
C114 C194 C195: library part CMP-0006199-2, "CAP, CERM, 0.47 uF, 6.3 V, +/- 10%, X5R, 0402", Cap_Case=0402, Manufacturer=AVX, Supplier Part Number 1=478-6196-1-ND, TempCo=X5R, Tolerance_%=10%, Value1=Unknown, Value2=6.3V, ValueDisplayed=0.47uF
C125 C126 C130 C131 C135 C142 C144: library part CMP-0096736-1, "10 µF ±20% 25V Ceramic Capacitor X5R 0603 (1608 Metric)", Manufacturer=Wurth, Operating Temperature Range="-55°C to +85°C", TempCo=15%, Temperature Characteristic=X5R, Tolerance_%=20%, ValueDisplayed=10uF
C127 C128 C132 C133 C136 C137 C143: library part CMP-0006618-2, "CAP, CERM, 0.1 uF, 100 V, +/- 10%, X5R, 0402", Cap_Case=0402, Manufacturer=MuRata, Supplier Part Number 1=490-10458-1-ND, TempCo=X5R, Tolerance_%=10%, Value1=Unknown, Value2=100V, ValueDisplayed=0.1uF
C134: library part CMP-0006354-2, "CAP, CERM, 1000 pF, 50 V, +/- 10%, X7R, AEC-Q200 Grade 1, 0402", Cap_Case=0402, Manufacturer=MuRata, Supplier Part Number 1=490-4761-1-ND, TempCo=X7R, Tolerance_%=10%, Value1=Unknown, Value2=50V, ValueDisplayed=1000pF
C140 C156 C157 C158 C165: library part CMP-0085568-1, "CAP, CERM, 0.01 µF, 25 V,+/- 5%, X7R, 0402", Cap_Case=0402, Manufacturer=AVX, TempCo=X7R, Tolerance_%=5%, Value2=25V, ValueDisplayed=0.01µF
C159 C160: library part CMP-0087060-3, "Cap Ceramic 8pF 50V C0G 0.5pF SMD 0402 125C Paper T/R", Manufacturer="Murata Electronics North America", TempCo=30ppm/°C
C161: library part CMP-0006216-2, "CAP, CERM, 15 pF, 50 V, +/- 5%, C0G/NP0, 0402", Cap_Case=0402, Manufacturer="Wurth Elektronik", Supplier Part Number 1=710-885012005056, TempCo=C0G/NP0, Tolerance_%=5%, Value1=Unknown, Value2=50V, ValueDisplayed=15pF
C166 C169: library part CMP-0860551-1, "CAP, CERM, 3.3 µF, 16 V,+/- 10%, X7R, 0805", Cap_Case=0805, Manufacturer=TDK, TempCo=X7R, Tolerance_%=10%, Value2=16V, ValueDisplayed=3.3µF
C181: library part CMP-0097305-1, "4.7 µF ±20% 10V Ceramic Capacitor X5R 0603 (1608 Metric)", Digikey Part Number=732-7909-1-ND, Manufacturer="Wurth Electronics", Mouser Part Number=710-885012106012, Operating Temperature Range="-55°C to +85°C", TempCo=15%, Temperature Characteristic=X5R, Tolerance_%=20%, ValueDisplayed=4.7uF
C187: library part CMP-0078624-1, "CAP, CERM, 10 µF, 6.3 V,+/- 20%, X5R, 0402", Cap_Case=0402, Manufacturer=MuRata, Supplier Part Number 1=490-13239-1-ND, TempCo=X5R, Tolerance_%=20%, Value2=6.3V, ValueDisplayed=10µF
C206: library part CMP-0007027-4, "CAP, CERM, 3.3 uF, 16 V, +/- 10%, X6S, 0603", Cap_Case=0603, Manufacturer=TDK, Supplier Part Number 1=445-9096-1-ND, TempCo=X6S, Tolerance_%=10%, Value1="0.004796 ohm", Value2=16V, ValueDisplayed=3.3uF
D1 D2 D3 D4 D5 D6 D10 D11 D12 D13 D14 D15 D16 D17 D20 D23 D24: library part CMP-0002894-2, "LED, Green, SMD", Color=green, Manufacturer="Wurth Elektronik", Value1=W, Value2=2V
D7 D8: library part CMP-0125609-1, "Green, Red 520nm Green, 625nm Red LED Indication - Discrete 3.2V Green, 2V Red 0606 (1616 Metric)", Color="Red, Green", Digikey Part Number=732-150066RG74000CT-ND, Forward Current=20mA, Manufacturer=Wurth, Mouser Part Number=710-150066RG74000, Operating Temperature Range="-40°C to +85°C"
D18 D22: library part CMP-0005599-2, "Diode, TVS, Bi, 6.5 V, SMB", Manufacturer=Littelfuse, Value1=600W
D19 D21: library part CMP-0002947-3, "LED, Red, SMD", Color=Red, Manufacturer="Wurth Elektronik", Power_TotalModule=72mW, Value1=0.072W, Value2=2V
F1: library part CMP-0003484-2, "Fuse, 2 A, 125VAC/VDC, SMD", Irating_A=2A, Manufacturer=Littelfuse, Supplier Part Number 1=F3145CT-ND
FID1 FID2 FID3 FID4 FID5 FID6: library part CMP-0077181-1, "Fiducial mark.  There is nothing to buy or mount.", Manufacturer=N/A
H1 H2: library part CMP-0003617-1, "Machine Screw, Round, #4-40 x 1/4, Nylon, Philips panhead", Manufacturer="B&F Fastener Supply", Supplier Part Number 1=H542-ND
J1: library part CMP-0075222-1, "DC POWER JACK, R/A, TH", Color=Black, Current_A=5A, Manufacturer="CUI Inc.", Supplier Part Number 1=CP-102AH-ND, Voltage_V=24V
J2 J3: library part CMP-0065699-1, "1 Port RJ45Surface Mount 10/100 Base-T, AutoMDIX", Digikey Part Number=732-4495-5-ND, Manufacturer="Wurth Electronics", Mouser Part Number=710-7498011211, Operating Temperature Range="-40°C to +85°C"
J4: library part CMP-0043004-2, "2 Pin Screw Terminal, Power Tap M3 Surface Mount, Right Angle", Current_A=50A, Digikey Part Number=732-10897-1-ND, Manufacturer="Wurth Electronics", Mouser Part Number=710-7466313R, Operating Temperature Range="-55°C to +150°C"
J5 J17 J18 J20: library part CMP-0054794-2, "Header, 2.54 mm, 2x1, Gold, TH", Color=Black, Manufacturer="Wurth Elektronik", Supplier Part Number 1=732-5315-ND
J6: library part CMP-0078832-1, "MicroSD Card Connector, R/A, Gold, SMT", Color=Black, Current_A=5dA, Manufacturer="Wurth Elektronik", Supplier Part Number 1=732-3819-1-ND, Voltage_V=100V
J7 J8: library part CMP-0054802-2, "Header, 2.54mm, 3x2, Gold, TH", Color=Black, Manufacturer="Wurth Elektronik", Supplier Part Number 1=732-5295-ND
J9: library part CMP-0054806-3, "Header, 2.54 mm, 5x2, Gold, TH", Current_A=3A, Manufacturer="Wurth Elektronik", Supplier Part Number 1=732-2672-ND, Voltage_V=250V
J10: library part CMP-0092423-1, "THT Vertical Pin Header WR-PHD, Pitch 2.54 mm, Dual Row, 12 pins", Current_A=3A, Digikey Part Number=732-5297-ND, Manufacturer="Wurth Electronics", Mouser Part Number=710-61301221121, Operating Temperature Range="-40°C to +105°C", Voltage_V=250V
J11: library part CMP-0075524-1, "Receptacle, 0.5 mm, 30x2, Gold, TH", Color=Black, Manufacturer=Samtec, Supplier Part Number 1=SAM8180-ND
J12: library part CMP-0054796-4, "Header, 2.54 mm, 3x1, Gold, TH", Manufacturer="Wurth Elektronik", Supplier Part Number 1=732-5316-ND
J13 J15: library part CMP-0097752-1, "Conn Micro USB 2.0 Type AB RCP 5 POS 0.65mm Solder RA SMD 5 Terminal 1 Port T/R", Current_A=1A, Digikey Part Number=732-5961-1-ND, Manufacturer="Wurth Electronics", Mouser Part Number=710-629105150921, Operating Temperature Range="-40°C to +85°C", Voltage_V=30V
J14: library part CMP-0091586-1, "USB-C (USB TYPE-C) USB 3.2 Gen 2 (USB 3.1 Gen 2, Superspeed + (USB 3.1)) Receptacle Connector 24 Position Surface Mount, Right Angle; Through Hole", Current_A=5A, Digikey Part Number=732-9618-1-ND, Manufacturer=Wurth, Mouser Part Number=710-632723300011, Operating Temperature Range="-40°C to +105°C", Voltage_V=20V
J16: library part CMP-0075640-2, "Header, 1.27mm, 10x2, Tin, SMT", Color=Black, Current_A=3.1A, Manufacturer=Samtec, Supplier Part Number 1=SAM8792-ND
L1 L2 L3: library part CMP-0064306-1, "Inductor, Shielded, 470 nH, 1.5 A, 0.1 ohm, SMD", Manufacturer="Wurth Elektronik", Supplier Part Number 1=732-9704-1-ND, Value1="0.1 ohm", Value2=1.5A, ValueDisplayed=470nH
L4_SOM-ETH1 L4_SOM-ETH2 L5_SOM-ETH1 L5_SOM-ETH2 L17 L18: library part CMP-0003175-2, "Ferrite Bead, 22 ohm @ 100 MHz, 1 A, 0603", Manufacturer="Wurth Elektronik", Supplier Part Number 1=732-1597-1-ND, Value1="0.05 ohm", Value2=1A, ValueDisplayed="22 ohm"
L6: library part CMP-0063784-1, "Inductor, Shielded Drum Core, Ferrite, 2.5 uH, 1.25 A, 0.05 ohm, SMD", Manufacturer="Wurth Elektronik", Supplier Part Number 1=732-1006-1-ND, Value1="0.05 ohm", Value2=1.25A, ValueDisplayed=2.5uH
L7: library part CMP-0003112-1, "Ferrite Bead, 120 ohm @ 100 MHz, 3 A, 1206", Manufacturer="Wurth Elektronik", Supplier Part Number 1=732-1622-1-ND, Value1="0.03 ohm", Value2=3A, ValueDisplayed="120 ohm"
L8: library part CMP-0127118-1, "330 µH @ 100 kHz 2 Line Common Mode Choke Surface Mount 2 kOhms @ 20 MHz 300mA DCR 300mOhm", Digikey Part Number=732-3939-1-ND, Manufacturer="Wurth Electronics", Mouser Part Number=710-744212331, Operating Temperature Range="-40°C to +105°C", Test Frequency=10kHz, Tolerance_%=50%
L9 L12: library part CMP-0003091-1, "Ferrite Bead, 30 ohm @ 100 MHz, 3 A, 0805", Manufacturer="Wurth Elektronik", Supplier Part Number 1=732-1611-1-ND, Value1="0.025 ohm", Value2=3A, ValueDisplayed="30 ohm"
L10 L11: library part CMP-0125765-1, "2 Line Common Mode Choke Surface Mount 90 Ohms @ 100 MHz 280mA DCR 300mOhm", Digikey Part Number=732-2578-1-ND, Impedance At Frequency="90Ω @ 100MHz", Manufacturer=Wurth, Mouser Part Number=710-744233900, Operating Temperature Range="-40°C to +105°C", Voltage=50V
L13 L14 L15: library part CMP-0003214-1, "Ferrite Bead, 120 ohm @ 100 MHz, 0.5 A, 0402", Manufacturer="Wurth Elektronik", Supplier Part Number 1=710-74279271, Value1="0.2 ohm", Value2=0.5A, ValueDisplayed="120 ohm"
L16: library part CMP-0003200-2, "Ferrite Bead, 1000 ohm @ 100 MHz, 0.2 A, 0603", Manufacturer="Wurth Elektronik", Supplier Part Number 1=732-4484-1-ND, Value1="0.6 ohm", Value2=0.2A, ValueDisplayed="1000 ohm"
LBL1: library part CMP-0003625-1, "Thermal Transfer Printable Labels, 0.650\" W x 0.200\" H - 10,000 per roll", Manufacturer=Brady, Supplier Part Number 1=97C5133
Logo1: library part CMP-0074838-1, "Texas Instrument Corporate Signature"
Logo2: library part CMP-0074844-2, Manufacturer="Texas Instruments"
Logo3: library part CMP-0074847-1, "FCC_disclaimer"
Logo4: library part CMP-0074769-4, Manufacturer="Texas Instruments"
MH1 MH2 MH3 MH4: library part CMP-0078424-2, "PCB Mounting Hole, No Pad", Manufacturer=Any, PartNumber=N/A
Q1: library part CMP-0090098-1, "100mA 45V NPN Signal Transistor DFN0806", Collector Base Voltage=50V, Digikey Part Number=BC847BFA-7BDICT-ND, Emitter Base Voltage=6V, Manufacturer="Diodes Inc.", Mouser Part Number=621-BC847BFA-7B, Operating Temperature Range="-55°C to +150°C", Power_W=435mW, Unity Gain Freq=170MHz
Q2 Q5 Q6 Q7 Q8 Q9 Q10 Q11 Q12 Q13 Q14: library part CMP-0000198-1, "MOSFET, N-CH, 12 V, 2.9 A, YJC0003A (PICOSTAR-3)", Alternate Manufacturer=None, Manufacturer="Texas Instruments", Supplier Part Number 1=296-39991-1-ND, Value1=0.04, Value2="2 nC"
Q3 Q4: library part CMP-0000968-2, "MOSFET, N-CH, 100 V, 4.5 A, DQK0006C (WSON-6)", Alternate Manufacturer=None, Manufacturer="Texas Instruments"
R1 R6 R7 R8 R9 R10 R12 R14 R15 R21 R24_SOM-ETH1 R24_SOM-ETH2 R25_SOM-ETH1 R25_SOM-ETH2 R27_SOM-ETH1 R27_SOM-ETH2 R33 R34 R35 R36 R55 R56 R57 R93 R95 R99 R100 R103 R105 R107 R114 R115 R116 R117 R118 R119 R124 R125 R126 R127 R133 R134 R136 R137 R140 R141 R142 R164 R169 R171 R172 R173 R175 R176 R177 R178 R179 R180 R181 R187 R188 R189 R192 R193 R213 R214 R220 R221 R239 R240 R241 R242: library part CMP-0025958-3, "RES, 10.0 k, 1%, 0.063 W, AEC-Q200 Grade 0, 0402", Manufacturer=Vishay-Dale, Power_W=63mW, Supplier Part Number 1=541-10.0KLCT-ND, TempCo="100 ppm/C", Tolerance_%=1%, Value2=0.063W, Value_Code=10k0, ValueDisplayed=10.0k
R2 R96: library part CMP-0026240-2, "RES, 2.67 k, 1%, 0.063 W, AEC-Q200 Grade 0, 0402", Manufacturer=Vishay-Dale, Power_W=63mW, Supplier Part Number 1=541-2.67KLCT-ND, TempCo="100 ppm/C", Tolerance_%=1%, Value2=0.063W, Value_Code=2k67, ValueDisplayed=2.67k
R3 R4 R5 R89 R91 R94: library part CMP-0026849-3, "RES, 180, 5%, 0.063 W, AEC-Q200 Grade 0, 0402", Manufacturer=Vishay-Dale, Power_W=63mW, Supplier Part Number 1=541-180JCT-ND, TempCo="200 ppm/C", Tolerance_%=5%, Value2=0.063W, Value_Code=180R, ValueDisplayed=180
R11 R51 R64 R128 R129 R130 R131 R151 R152 R154 R155 R156 R157 R158 R159 R160 R161 R165 R190 R194 R195 R196 R197 R202: library part CMP-0026071-3, "RES, 1.00 k, 1%, 0.063 W, AEC-Q200 Grade 0, 0402", Manufacturer=Vishay-Dale, Power_W=63mW, Supplier Part Number 1=541-1.00KLCT-ND, TempCo="100 ppm/C", Tolerance_%=1%, Value2=0.063W, Value_Code=1k00, ValueDisplayed=1.00k
R13 R17 R217 R219: library part CMP-0027743-1, "RES, 4.70 k, 1%, 0.05 W, 0201", Manufacturer="Yageo America", Power_W=50mW, Supplier Part Number 1=311-4.70KMCT-ND, TempCo="200 ppm/C", Tolerance_%=1%, Value2=0.05W, Value_Code=4k70, ValueDisplayed=4.70k
R16 R120 R121 R123: library part CMP-0027262-3, "RES, 10.0 k, 1%, 0.05 W, 0201", Manufacturer=Vishay-Dale, Power_W=50mW, Supplier Part Number 1=541-10.0KAABCT-ND, TempCo="100 ppm/C", Tolerance_%=1%, Value2=0.05W, Value_Code=10k0, ValueDisplayed=10.0k
R18 R19 R20 R198 R223 R224 R225: library part CMP-0026759-1, "RES, 33.0, 1%, 0.063 W, AEC-Q200 Grade 0, 0402", Manufacturer="Stackpole Electronics Inc", Power_W=63mW, Supplier Part Number 1=RMCF0402FT33R0CT-ND, TempCo="100 ppm/C", Tolerance_%=1%, Value2=0.063W, Value_Code=33R0, ValueDisplayed=33.0
R22 R145 R186 R199 R200 R215: library part CMP-0026822-3, "RES, 0, 5%, 0.063 W, AEC-Q200 Grade 0, 0402", Manufacturer=Vishay-Dale, Power_W=63mW, Supplier Part Number 1=541-0.0JCT-ND, TempCo="200 ppm/C", Tolerance_%=5%, Value2=0.063W, Value_Code=0000, ValueDisplayed=0
R23_SOM-ETH1 R23_SOM-ETH2 R233_SOM-ETH1 R233_SOM-ETH2: library part CMP-0026231-2, "RES, 2.20 k, 1%, 0.063 W, AEC-Q200 Grade 0, 0402", Manufacturer=Vishay-Dale, Power_W=63mW, Supplier Part Number 1=541-2.20KLCT-ND, TempCo="100 ppm/C", Tolerance_%=1%, Value2=0.063W, Value_Code=2k20, ValueDisplayed=2.20k
R26_SOM-ETH1 R26_SOM-ETH2: library part CMP-0026515-2, "RES, 6.49 k, 1%, 0.063 W, AEC-Q200 Grade 0, 0402", Manufacturer=Vishay-Dale, Power_W=63mW, Supplier Part Number 1=541-6.49KLCT-ND, TempCo="100 ppm/C", Tolerance_%=1%, Value2=0.063W, Value_Code=6k49, ValueDisplayed=6.49k
R28_SOM-ETH1 R28_SOM-ETH2 R204_SOM-ETH1 R204_SOM-ETH2 R205_SOM-ETH1 R205_SOM-ETH2 R206_SOM-ETH1 R206_SOM-ETH2: library part CMP-0026088-3, "RES, 1.50 k, 1%, 0.063 W, AEC-Q200 Grade 0, 0402", Manufacturer=Vishay-Dale, Power_W=63mW, Supplier Part Number 1=541-1.50KLCT-ND, TempCo="100 ppm/C", Tolerance_%=1%, Value2=0.063W, Value_Code=1k50, ValueDisplayed=1.50k
R29_SOM-ETH1 R29_SOM-ETH2 R30_SOM-ETH1 R30_SOM-ETH2 R31_SOM-ETH1 R31_SOM-ETH2 R32_SOM-ETH1 R32_SOM-ETH2 R201_SOM-ETH1 R201_SOM-ETH2 R207_SOM-ETH1 R207_SOM-ETH2: library part CMP-0026237-2, "RES, 2.49 k, 1%, 0.063 W, AEC-Q200 Grade 0, 0402", Manufacturer=Vishay-Dale, Power_W=63mW, Supplier Part Number 1=541-2.49KLCT-ND, TempCo="100 ppm/C", Tolerance_%=1%, Value2=0.063W, Value_Code=2k49, ValueDisplayed=2.49k
R37 R38 R40 R41 R42 R43 R44 R66 R67 R69 R70 R71 R72 R73: library part CMP-0027732-1, "RES, 49.9 k, 1%, 0.05 W, 0201", Manufacturer="Yageo America", Power_W=50mW, Supplier Part Number 1=YAG2701CT-ND, TempCo="200 ppm/C", Tolerance_%=1%, Value2=0.05W, Value_Code=49k9, ValueDisplayed=49.9k
R39 R68: library part CMP-0027280-3, "RES, 4.70 k, 1%, 0.05 W, 0201", Manufacturer=Vishay-Dale, Power_W=50mW, Supplier Part Number 1=541-4.70KAABCT-ND, TempCo="100 ppm/C", Tolerance_%=1%, Value2=0.05W, Value_Code=4k70, ValueDisplayed=4.70k
R45 R46 R47 R48 R49 R50 R53 R54 R74 R75 R76 R77 R78 R79 R80 R81 R82 R183 R212 R226 R227 R228 R229 R230 R231: library part CMP-0027074-3, "RES, 22, 5%, 0.05 W, 0201", Manufacturer="Yageo America", Power_W=50mW, Supplier Part Number 1=311-22NCT-ND, TempCo="200 ppm/C", Tolerance_%=5%, Value2=0.05W, Value_Code=22R0, ValueDisplayed=22
R52 R58 R108 R109 R110 R111 R191: library part CMP-0025950-3, "RES, 100 k, 1%, 0.063 W, AEC-Q200 Grade 0, 0402", Manufacturer=Vishay-Dale, Power_W=63mW, Supplier Part Number 1=541-100KLCT-ND, TempCo="100 ppm/C", Tolerance_%=1%, Value2=0.063W, Value_Code=100k
R59: library part CMP-0026310-2, "RES, 35.7 k, 1%, 0.063 W, AEC-Q200 Grade 0, 0402", Manufacturer=Vishay-Dale, Power_W=63mW, Supplier Part Number 1=541-35.7KLCT-ND, TempCo="100 ppm/C", Tolerance_%=1%, Value2=0.063W, Value_Code=35k7, ValueDisplayed=35.7k
R60: library part CMP-0026367-2, "RES, 40.2 k, 1%, 0.063 W, AEC-Q200 Grade 0, 0402", Manufacturer=Vishay-Dale, Power_W=63mW, Supplier Part Number 1=541-40.2KLCT-ND, TempCo="100 ppm/C", Tolerance_%=1%, Value2=0.063W, Value_Code=40k2, ValueDisplayed=40.2k
R61: library part CMP-0026003-3, "RES, 13.0 k, 1%, 0.063 W, AEC-Q200 Grade 0, 0402", Manufacturer=Vishay-Dale, Power_W=63mW, Supplier Part Number 1=541-13.0KLCT-ND, TempCo="100 ppm/C", Tolerance_%=1%, Value2=0.063W, Value_Code=13k0, ValueDisplayed=13.0k
R62: library part CMP-0026769-2, "RES, 10.0 k, 0.5%, 0.063 W, AEC-Q200 Grade 0, 0402", Manufacturer=Vishay-Dale, Power_W=63mW, Supplier Part Number 1=541-10KAVCT-ND, TempCo="50 ppm/C", Tolerance_%=0.5%, Value2=0.063W, Value_Code=10k0, ValueDisplayed=10.0k
R63 R65: library part CMP-0026542-2, "RES, 750, 1%, 0.063 W, AEC-Q200 Grade 0, 0402", Manufacturer=Vishay-Dale, Power_W=63mW, Supplier Part Number 1=541-750LCT-ND, TempCo="100 ppm/C", Tolerance_%=1%, Value2=0.063W, Value_Code=750R, ValueDisplayed=750
R83 R182 R184 R185 R208 R209 R210 R211 R232 R234 R235 R236 R237 R238: library part CMP-0027008-4, "RES, 0, 5%, 0.05 W, 0201", Manufacturer=Vishay-Dale, Power_W=50mW, Supplier Part Number 1=72M6743, TempCo=ppm/C, Tolerance_%=5%, Value2=0.05W, Value_Code=0000, ValueDisplayed=0
R84 R85 R86 R87 R90 R92: library part CMP-0081786-1, "RES, 220, 5%, 0.063 W, AEC-Q200 Grade 0, 0402", Manufacturer=Vishay-Dale, Power_W=63mW, Supplier Part Number 1=CRCW0402220RJNTD-ND, TempCo="200 ppm/C", Tolerance_%=5%, Value2=0.063W, Value_Code=220R, ValueDisplayed=220
R88 R139 R144 R153 R162: library part CMP-0016296-3, "RES, 1.00 M, 1%, 0.75 W, AEC-Q200 Grade 0, 2010", Manufacturer=Vishay-Dale, Power_W=750mW, Supplier Part Number 1=541-1.0MACCT-ND, TempCo="100 ppm/C", Tolerance_%=1%, Value2=0.75W, Value_Code=1M00, ValueDisplayed=1.00M
R98 R112 R113 R146: library part CMP-0025951-3, "RES, 100, 1%, 0.063 W, AEC-Q200 Grade 0, 0402", Manufacturer=Vishay-Dale, Power_W=63mW, Supplier Part Number 1=541-100LCT-ND, TempCo="100 ppm/C", Tolerance_%=1%, Value2=0.063W, Value_Code=100R, ValueDisplayed=100
R122 R163: library part CMP-0026404-2, "RES, 49.9, 1%, 0.063 W, AEC-Q200 Grade 0, 0402", Manufacturer=Vishay-Dale, Power_W=63mW, Supplier Part Number 1=541-49.9LCT-ND, TempCo="100 ppm/C", Tolerance_%=1%, Value2=0.063W, Value_Code=49R9, ValueDisplayed=49.9
R132: library part CMP-0025967-3, "RES, 110 k, 1%, 0.063 W, AEC-Q200 Grade 0, 0402", Manufacturer=Vishay-Dale, Power_W=63mW, Supplier Part Number 1=541-110KLCT-ND, TempCo="100 ppm/C", Tolerance_%=1%, Value2=0.063W, Value_Code=110k
R135: library part CMP-0026158-2, "RES, 200 k, 1%, 0.063 W, AEC-Q200 Grade 0, 0402", Manufacturer=Vishay-Dale, Power_W=63mW, Supplier Part Number 1=541-200KLCT-ND, TempCo="100 ppm/C", Tolerance_%=1%, Value2=0.063W, Value_Code=200k
R138: library part CMP-0026603-2, "RES, 909 k, 1%, 0.063 W, AEC-Q200 Grade 0, 0402", Manufacturer=Vishay-Dale, Power_W=63mW, Supplier Part Number 1=541-909KLCT-ND, TempCo="100 ppm/C", Tolerance_%=1%, Value2=0.063W, Value_Code=909k
R143: library part CMP-0026534-2, "RES, 715, 1%, 0.063 W, AEC-Q200 Grade 0, 0402", Manufacturer=Vishay-Dale, Power_W=63mW, Supplier Part Number 1=541-715LCT-ND, TempCo="100 ppm/C", Tolerance_%=1%, Value2=0.063W, Value_Code=715R, ValueDisplayed=715
R147 R148: library part CMP-0078210-2, "RES, 330 k, 1%, 0.063 W, AEC-Q200 Grade 0, 0402", Manufacturer=Vishay-Dale, Power_W=63mW, Supplier Part Number 1=541-330KLCT-ND, TempCo="100 ppm/C", Tolerance_%=1%, Value2=0.063W, Value_Code=330k
R149 R150: library part CMP-0026910-3, "RES, 360, 5%, 0.063 W, AEC-Q200 Grade 0, 0402", Manufacturer=Vishay-Dale, Power_W=63mW, Supplier Part Number 1=541-360JCT-ND, TempCo="200 ppm/C", Tolerance_%=5%, Value2=0.063W, Value_Code=360R, ValueDisplayed=360
R166: library part CMP-0026437-2, "RES, 51.1 k, 1%, 0.063 W, AEC-Q200 Grade 0, 0402", Manufacturer=Vishay-Dale, Power_W=63mW, Supplier Part Number 1=541-51.1KLCT-ND, TempCo="100 ppm/C", Tolerance_%=1%, Value2=0.063W, Value_Code=51k1, ValueDisplayed=51.1k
